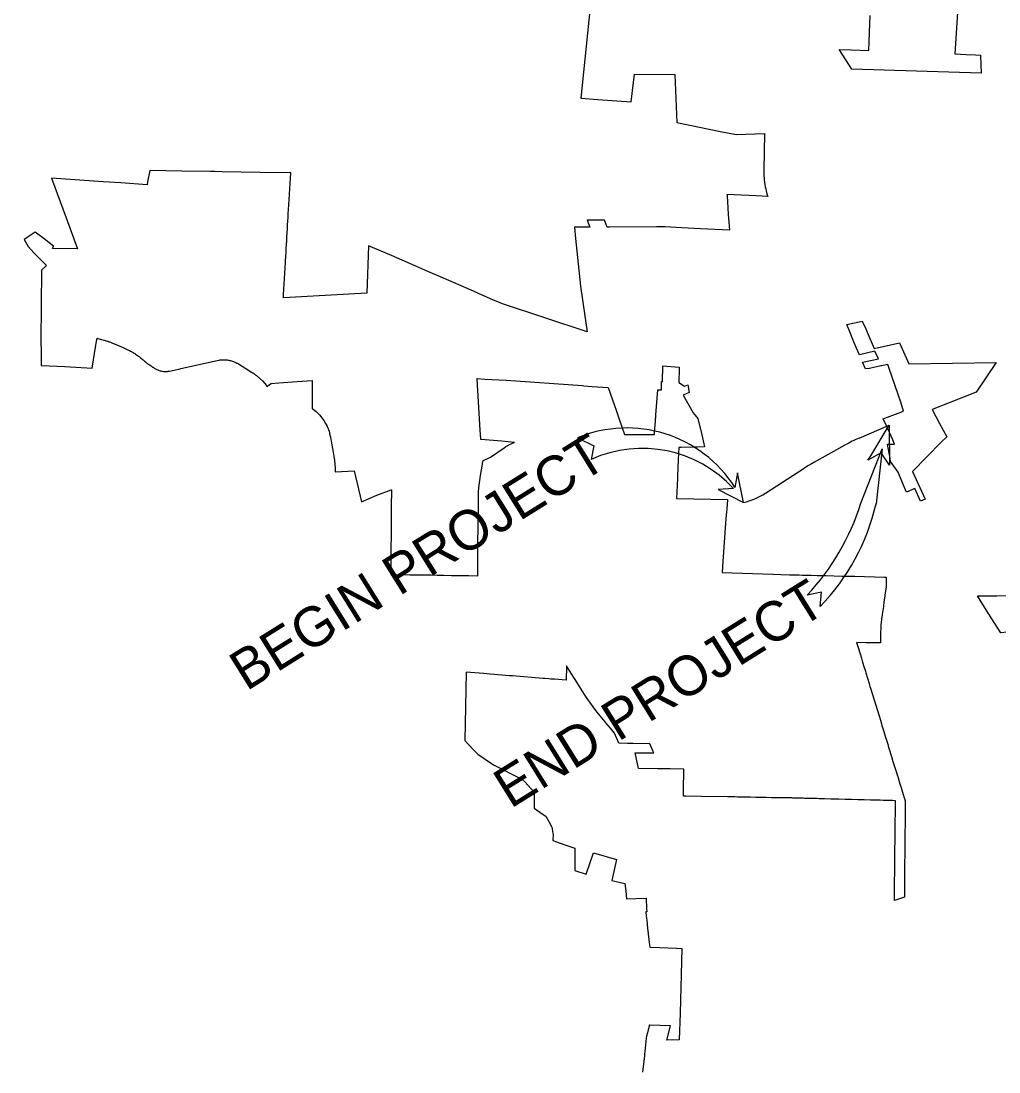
# Model space of a CAD drawing. Extents: x 2038094 to 2053858, y 751760 to 764312.
# Drawn here: x 2043353 to 2044647, y 758364 to 759754 of the extents above; entities that cross this region are included whole.
import ezdxf

# ---------------------------------------------------------------- set-up
doc = ezdxf.new("R2010")
doc.units = 0
for name, color, linetype in [('Old_Level_14', 7, 'Continuous'), ('Prop Horizontal Alignment', 7, 'Continuous'), ('Prop Shade Light', 7, 'Continuous'), ('Sheet Title CELL', 7, 'Continuous')]:
    doc.layers.add(name, color=color, linetype=linetype)

msp = doc.modelspace()

# ---------------------------------------------------------------- linework, layer by layer
at = {"layer": 'Old_Level_14'}
for p, q in [((2044463.9, 759116.1), (2044492.2, 759187.9)), ((2044492.2, 759187.9), (2044484.1, 759115.2)), ((2044295.5, 759135.4), (2044275.2, 759134))]:
    msp.add_line(p, q, dxfattribs=at)
msp.add_lwpolyline([(2044477.3, 759178.5), (2044501.4, 759219.1), (2044501.7, 759166.2), (2044490.9, 759182.5), (2044473.1, 759173)], close=True, dxfattribs=at)
for points in [[(2044089, 759202.3), (2044111, 759192), (2044107.5, 759173.9)], [(2044275.2, 759134), (2044308.7, 759116.8), (2044300.7, 759156.2), (2044297.5, 759136.9)], [(2044410.3, 758979.3), (2044411.8, 758998.1), (2044393, 758994.5)]]:
    msp.add_lwpolyline(points, dxfattribs=at)
for centre, radius, start, end in [((2044154.4, 759045.7), 169.7, 32.5095, 112.6622), ((2044174.8, 759024), 164.3, 42.6841, 114.1812), ((2044166.8, 759208), 311, 316.6494, 342.8091), ((2044206, 759178.3), 285.1, 315.7478, 347.23)]:
    msp.add_arc(centre, radius, start, end, dxfattribs=at)
at = {"layer": 'Prop Horizontal Alignment'}
for p, q in [((2044461.9, 759202.1), (2044501.4, 759219.1)), ((2044402.1, 759170), (2044443.4, 759193)), ((2044337.7, 759129.2), (2044389, 759162.1))]:
    msp.add_line(p, q, dxfattribs=at)
for centre, radius, start, end in [((2044540.8, 759018.3), 200, 113.2527, 119.1633), ((2044524, 758951.7), 250, 119.1633, 122.6814), ((2044286.4, 759209.1), 95, 283.6056, 302.6814)]:
    msp.add_arc(centre, radius, start, end, dxfattribs=at)
at = {"layer": 'Prop Shade Light'}
for points in [[(2044106.1, 759771.8), (2044093.7, 759651.7), (2044116, 759649.9), (2044160, 759646.7), (2044164.4, 759683.1), (2044217.8, 759682.8), (2044220.6, 759619.4), (2044278.3, 759607.6), (2044299, 759603.4), (2044336.6, 759604.6), (2044335.6, 759556.9), (2044335.6, 759554.6), (2044335.6, 759551.5), (2044335.7, 759548.6), (2044335.9, 759546.3), (2044336.1, 759543.6), (2044336.5, 759540.7), (2044337, 759536.8), (2044337.5, 759534.2), (2044338.1, 759531.6), (2044338.7, 759529), (2044339.7, 759525.1), (2044340.8, 759521.7), (2044325.7, 759522.3), (2044286.9, 759524), (2044287, 759523.6), (2044287.1, 759522.3), (2044288.1, 759506.3), (2044288.7, 759497.5), (2044289.4, 759487.7), (2044290.1, 759477.1), (2044251.9, 759478.9), (2044227.1, 759480.1), (2044205, 759481.2), (2044193.8, 759481.2), (2044131.7, 759481), (2044128.6, 759481), (2044125, 759490.3), (2044122, 759490.3), (2044102, 759490.2), (2044105.4, 759481), (2044099.5, 759481), (2044085.3, 759480.9), (2044086.7, 759466.1), (2044091.9, 759415.6), (2044093.2, 759403), (2044102, 759342.4), (2043990.2, 759379.4), (2043977.3, 759385), (2043959, 759392.9), (2043956.3, 759394.1), (2043951.6, 759396.2), (2043908.7, 759414.8), (2043891.1, 759422.4), (2043875.3, 759429.3), (2043843, 759443.3), (2043813, 759456.4), (2043810.7, 759393.6), (2043700.2, 759387.5), (2043700.4, 759392.1), (2043702.9, 759434.1), (2043703, 759436.3)], [(2044591.8, 759764.8), (2044588.3, 759710), (2044603.3, 759709.3), (2044615.7, 759708.8), (2044622.1, 759708.2), (2044622.2, 759707.6), (2044623.1, 759684.5), (2044451.9, 759689.7), (2044435.4, 759715.9), (2044451, 759715.4), (2044474.4, 759714.6), (2044474.9, 759726.8), (2044476.1, 759760.8)], [(2043703, 759436.3), (2043703.3, 759442.1), (2043703.7, 759447.9), (2043704, 759453), (2043704.3, 759458), (2043704.6, 759463), (2043704.9, 759468), (2043705.1, 759473), (2043705.5, 759478.9), (2043705.8, 759483.9), (2043706.1, 759488.9), (2043706.4, 759493.9), (2043706.7, 759498.9), (2043707, 759504.1), (2043707.3, 759510.5), (2043707.7, 759517.4), (2043708.2, 759524.5), (2043709.9, 759552.8), (2043709.7, 759552.8), (2043669.7, 759553.4), (2043619.3, 759554.2), (2043609.3, 759554.5), (2043603.7, 759554.6), (2043566, 759555.2), (2043523.4, 759555.9), (2043520.7, 759541), (2043519.9, 759536.9), (2043485.4, 759539.4), (2043461.7, 759541.1), (2043449.3, 759541.9), (2043393.6, 759545.7), (2043412.9, 759493.4), (2043428.1, 759452.3), (2043394.9, 759452.8), (2043396, 759455.7), (2043383.7, 759465.3), (2043372.1, 759474.4), (2043357.5, 759464.5), (2043362.7, 759455.3), (2043371.1, 759446.1), (2043382.8, 759434.3), (2043386.8, 759430.3), (2043380.5, 759423.9), (2043379.5, 759330.7), (2043380, 759315.9), (2043379.9, 759298), (2043411.1, 759296.5), (2043447.4, 759294.7), (2043452.2, 759325), (2043452.6, 759327.7), (2043453.8, 759334.1), (2043454.6, 759333.9), (2043454.9, 759333.8), (2043467.7, 759330.1), (2043468.1, 759330), (2043468.8, 759329.8), (2043469.5, 759329.5), (2043470.7, 759329.1), (2043471.7, 759328.7), (2043472.6, 759328.4), (2043473.5, 759328), (2043474.4, 759327.6), (2043479.8, 759325.3), (2043489, 759321.2), (2043494.5, 759318.7), (2043495.3, 759318.4), (2043496.8, 759317.7), (2043497.9, 759317.1), (2043498.9, 759316.6), (2043499.7, 759316.2), (2043500.8, 759315.6), (2043501.7, 759315.1), (2043502.8, 759314.4), (2043503.7, 759313.8), (2043504.7, 759313.2), (2043506, 759312.3), (2043507.2, 759311.4), (2043508.4, 759310.5), (2043509.4, 759309.8), (2043510.3, 759309), (2043511.4, 759308.1), (2043512.4, 759307.3), (2043513.5, 759306.3), (2043514.6, 759305.4), (2043515.5, 759304.6), (2043516.5, 759303.9), (2043517.9, 759302.8), (2043518.9, 759302), (2043519.8, 759301.3), (2043520.6, 759300.7), (2043521.8, 759299.8), (2043523, 759298.9), (2043524, 759298.3), (2043525.3, 759297.4), (2043526.2, 759296.8), (2043527.3, 759296), (2043528, 759295.6), (2043528.8, 759295), (2043529.5, 759294.6), (2043530.3, 759294.1)], [(2044474.6, 759336.7), (2044478.9, 759326.7), (2044481.4, 759320.6), (2044515.3, 759327.9), (2044525.5, 759304.2), (2044527.3, 759300.1), (2044642.9, 759302.1), (2044616.4, 759262.8), (2044580.8, 759248.7), (2044558.3, 759239.8), (2044568.1, 759221.5), (2044577.5, 759203.9), (2044570.4, 759196.7), (2044532.3, 759158), (2044548.9, 759121.4), (2044542.7, 759118.4), (2044535.2, 759135.2), (2044524.4, 759130.5), (2044520.6, 759139.7), (2044514.3, 759154.8), (2044513.4, 759157.1), (2044503.3, 759171.2), (2044502.6, 759175.1), (2044499.3, 759193.9), (2044508.6, 759194), (2044506.1, 759199.6), (2044497.5, 759219), (2044493.5, 759227.5), (2044499.1, 759229.7), (2044520.5, 759237.8), (2044516.9, 759249.6), (2044501.4, 759294), (2044499.6, 759299.5), (2044491.5, 759297.6), (2044490.5, 759297.4), (2044475.6, 759294), (2044470.2, 759293.6), (2044466.3, 759302.6), (2044487.3, 759306.9), (2044482.6, 759317.1), (2044462.2, 759312.2), (2044458, 759321.9), (2044453.5, 759332.4), (2044449.2, 759342.4), (2044445.3, 759352.3), (2044465.9, 759356.5), (2044470.5, 759346.5), (2044474.6, 759336.7)], [(2043530.3, 759294.1), (2043531.1, 759293.7), (2043532, 759293.1), (2043532.1, 759293.1), (2043533, 759292.6), (2043534, 759292.2), (2043535, 759291.8), (2043536.1, 759291.4), (2043537.2, 759291.1), (2043538.4, 759290.8), (2043539.6, 759290.5), (2043541, 759290.3), (2043542.1, 759290.2), (2043543.4, 759290.1), (2043544.9, 759290.1), (2043546, 759290.2), (2043546.7, 759290.2), (2043546.9, 759290.3), (2043547.9, 759290.4), (2043548.8, 759290.5), (2043549.8, 759290.7), (2043563.7, 759293.8), (2043564.5, 759294), (2043612.6, 759304.8), (2043615.1, 759305.2), (2043616, 759305.4), (2043616.8, 759305.4), (2043617.9, 759305.5), (2043618.1, 759305.6), (2043619.4, 759305.6), (2043620.8, 759305.7), (2043622.2, 759305.6), (2043623.5, 759305.6), (2043625.2, 759305.4), (2043626, 759305.3), (2043627.1, 759305.2), (2043627.8, 759305.1), (2043628, 759305), (2043628.8, 759304.8), (2043630.1, 759304.5), (2043631.4, 759304.2), (2043633, 759303.7), (2043634.4, 759303.2), (2043635.8, 759302.6), (2043637.5, 759301.9), (2043638.8, 759301.2), (2043639.3, 759300.9), (2043640.9, 759300), (2043650.6, 759294), (2043658.1, 759289.4), (2043659.4, 759288.5), (2043659.9, 759288.2), (2043660.7, 759287.7), (2043661.6, 759287.1), (2043662.2, 759286.6), (2043662.8, 759286.2), (2043663.3, 759285.8), (2043663.9, 759285.4), (2043664.6, 759284.8), (2043665.2, 759284.4), (2043672.5, 759277.8), (2043675.8, 759274.1), (2043678.9, 759270.3), (2043682, 759272.7), (2043683.9, 759274.3), (2043694, 759275), (2043718.3, 759276.7), (2043738.4, 759278), (2043738.1, 759240.9), (2043739, 759240.5), (2043743.8, 759236.8), (2043747.8, 759232.6), (2043751, 759228.7), (2043753.6, 759225.1), (2043755.8, 759221.5), (2043756.7, 759220.1), (2043757.5, 759218.6), (2043758.2, 759217.2), (2043758.9, 759215.7), (2043759.5, 759214.2), (2043760.1, 759212.6), (2043760.6, 759211), (2043761, 759209.5), (2043761.4, 759207.8), (2043762.5, 759203.2), (2043763.4, 759197.8), (2043764.2, 759193), (2043765.1, 759188.2), (2043765.9, 759183.4), (2043766.9, 759178.3), (2043767.6, 759172.6), (2043768.2, 759167.5), (2043768.5, 759162.4), (2043768.6, 759157.2), (2043793.7, 759158.8), (2043803.7, 759117.6), (2043824, 759126.4), (2043842.7, 759133.6), (2043843, 759133.7), (2043843, 759127)], [(2044151.3, 759206.6), (2044151.9, 759206.6), (2044172.8, 759206.7), (2044191.1, 759206.8), (2044191.7, 759215.3), (2044192.3, 759223.6), (2044193, 759232.8), (2044195.4, 759265.8), (2044200.4, 759265.8), (2044200.5, 759276.6), (2044200.5, 759276.8), (2044201.8, 759276.7), (2044201.9, 759297.4), (2044223.5, 759295.7), (2044223.5, 759294), (2044223.2, 759275.7), (2044230.6, 759270.6), (2044235.1, 759272.3), (2044236.9, 759262.3), (2044228.9, 759259), (2044242.1, 759235.6), (2044248.5, 759227.9), (2044253.6, 759206.3), (2044257.4, 759190.3), (2044248, 759190), (2044243.7, 759189.9), (2044226.5, 759189.6), (2044223.4, 759189.5), (2044222.5, 759173.9), (2044221.5, 759151.8), (2044221.3, 759148.6), (2044220.2, 759122.2)], [(2044005.7, 759196.4), (2043989.1, 759197.8), (2043961.2, 759200.1), (2043961.2, 759201), (2043960.5, 759212.3), (2043957, 759272.4), (2043956.6, 759280.7), (2043966.6, 759280.1), (2043994.9, 759278.7), (2044095.8, 759271.4), (2044097.7, 759271.1), (2044103, 759270.5), (2044108.6, 759270.1), (2044129.9, 759269.1), (2044138.1, 759245.3), (2044140.3, 759238.9), (2044144.4, 759226.9), (2044151.3, 759206.6)], [(2043958.5, 759136.3), (2043961, 759152.4), (2043963.4, 759167.4), (2043964.1, 759172.1), (2043974.3, 759177), (2043992.2, 759189.2), (2043994.6, 759190.8), (2043997.1, 759192.2), (2044000.1, 759193.9), (2044003.1, 759195.2), (2044005.7, 759196.4)], [(2043843, 759127), (2043843, 759125), (2043842.9, 759119.9), (2043842.8, 759105.2), (2043842.8, 759095.1), (2043842.8, 759093.9), (2043842.7, 759080.5), (2043842.7, 759077.2), (2043842.6, 759068.9), (2043842.5, 759060.8), (2043842.5, 759053.3), (2043842.4, 759045.8), (2043842.4, 759038.3), (2043842.4, 759037), (2043842.4, 759033.3), (2043842.4, 759030.3), (2043842.4, 759022), (2043842.4, 759021.8), (2043849.8, 759021.7), (2043867.3, 759021.4), (2043868.1, 759021.4), (2043874.8, 759021.3), (2043878.5, 759021.3), (2043882.3, 759021.2), (2043887.3, 759021.1), (2043895.6, 759021), (2043903.8, 759020.8), (2043912.3, 759020.7), (2043922.4, 759020.5), (2043931.3, 759020.3), (2043939.8, 759020.2), (2043944.6, 759020.1), (2043945.3, 759020.1), (2043957.4, 759019.9), (2043957.5, 759036.3), (2043957.5, 759043.6), (2043957.5, 759051.1), (2043957.5, 759051.5), (2043957.5, 759061.4), (2043957.5, 759062.3), (2043957.6, 759070.2), (2043957.7, 759077.7), (2043957.8, 759085.2), (2043958, 759092.6), (2043958.1, 759100.1), (2043958.2, 759110.6), (2043958.3, 759118.1), (2043958.4, 759130.5), (2043958.5, 759136.3)], [(2044220.2, 759122.2), (2044221.1, 759122.2), (2044287.5, 759120.6), (2044287, 759113.8), (2044286.6, 759108.9)], [(2044286.6, 759108.9), (2044286.6, 759108.4), (2044286.2, 759103.9), (2044285.6, 759095.8), (2044281.5, 759038.9), (2044280.4, 759024.1), (2044347.6, 759022), (2044347.9, 759022), (2044358.1, 759021.6), (2044369.5, 759021.4), (2044374.3, 759021.3), (2044380.6, 759021.1), (2044382.3, 759021), (2044386.9, 759020.9), (2044390.5, 759020.8), (2044398.4, 759020.6), (2044406.1, 759020.5), (2044414.3, 759020.3), (2044417.7, 759020.2), (2044439.4, 759019.6), (2044439.8, 759019.6), (2044443.4, 759019.5), (2044444.4, 759019.5), (2044452.1, 759019.3), (2044452.4, 759019.3), (2044453.4, 759019.3), (2044455.4, 759019.3), (2044495.2, 759018.3), (2044497.4, 759018.2), (2044497.4, 759006.4), (2044497.4, 759005.2), (2044495.9, 758994.5), (2044495.7, 758992.8), (2044494.6, 758985.4), (2044493.8, 758979.5), (2044493, 758974), (2044492.2, 758968.6), (2044492.1, 758967.8), (2044491.4, 758963.1), (2044490.7, 758957.7), (2044490.4, 758955.7), (2044490.3, 758951.3), (2044490.1, 758943.9), (2044489.9, 758935.8), (2044489.8, 758931.2), (2044482.9, 758931.2), (2044471, 758931.3), (2044458.4, 758931.5), (2044460.4, 758925), (2044463, 758916.6), (2044464.7, 758911.2), (2044466.3, 758905.9), (2044468.1, 758900), (2044470, 758893.9), (2044470.5, 758891.7), (2044474.8, 758877.5), (2044475.6, 758875.1), (2044476, 758873.6), (2044476.8, 758871.2), (2044485.8, 758841.9), (2044490.2, 758827.6), (2044490.2, 758827.4), (2044492.3, 758820.7), (2044492.3, 758820.5), (2044494.3, 758814.1), (2044496.2, 758807.9), (2044498.3, 758801.2), (2044499.9, 758795.8), (2044500.3, 758794.5), (2044502.4, 758787.8), (2044504.2, 758781.7), (2044504.4, 758781.1), (2044506.5, 758774.4), (2044508.5, 758767.7), (2044510.6, 758761), (2044512.3, 758755.6), (2044512.7, 758754.3), (2044515.6, 758744.9), (2044517.1, 758739.9), (2044517.7, 758737.8)], [(2044699.2, 758994), (2044728.4, 758993.7), (2044730.8, 758986.8), (2044732.3, 758982.9), (2044734.4, 758977.4), (2044736.5, 758972.3), (2044738.8, 758966.7), (2044670.3, 758948.6), (2044671.5, 758946.6), (2044669.7, 758946.4), (2044657.5, 758945.2), (2044649, 758944.4), (2044636.4, 758964.4), (2044633.6, 758968.9), (2044632.5, 758970.5), (2044629.8, 758974.9), (2044621.6, 758987.9), (2044618.1, 758993.5), (2044640.4, 758993.5), (2044643.9, 758993.5), (2044669.7, 758994.1), (2044699.2, 758994)], [(2044155.4, 758798.2), (2044143.7, 758798.4), (2044138.3, 758811.8), (2044132.7, 758818.3), (2044126.5, 758825.6), (2044125.7, 758826.6), (2044117.1, 758837.3), (2044112.3, 758843.5), (2044107.7, 758849.8), (2044102.1, 758857.8), (2044097.8, 758864.3), (2044088.4, 758879.2), (2044078.1, 758895.3), (2044074.5, 758900.9), (2044074.5, 758900.1), (2044074.1, 758881.7), (2044058.9, 758883)], [(2044058.9, 758883), (2044053.8, 758883.4), (2044051.1, 758883.6), (2044045.8, 758884), (2044043.3, 758884.3), (2044003.1, 758887.5), (2043999.4, 758887.8), (2043973.5, 758890), (2043965.4, 758890.5), (2043964.7, 758890.5), (2043941.8, 758892.4), (2043940.9, 758846.6), (2043940, 758802), (2043951.3, 758790.3), (2043957.3, 758784), (2043978, 758770), (2044015.8, 758751.1), (2044019.4, 758747.3), (2044031.9, 758733.9), (2044032, 758712.6), (2044042.7, 758705.2), (2044047.4, 758702.1), (2044051.2, 758694.9), (2044055.1, 758687.7), (2044055.5, 758685.6), (2044056.2, 758681.4), (2044056.9, 758678), (2044056.4, 758669.7), (2044072.4, 758664.2), (2044085.8, 758659.9), (2044085.6, 758643.3), (2044085.6, 758638.6), (2044085.5, 758632.2), (2044085.8, 758630)], [(2044517.7, 758737.8), (2044518.6, 758735.1), (2044520.3, 758729.3), (2044520.9, 758727.7), (2044521.7, 758725.3), (2044522.7, 758722.2), (2044522.6, 758710.7), (2044522.6, 758705.7), (2044522.5, 758699.5), (2044522.5, 758694), (2044522.4, 758688.5), (2044522.3, 758683), (2044522.3, 758677.5), (2044522.2, 758671.5), (2044522.2, 758665.5), (2044522.1, 758660), (2044522.1, 758654.5), (2044522, 758648.8), (2044521.9, 758642.6), (2044521.9, 758636.2), (2044521.8, 758629.8), (2044521.8, 758623.2), (2044521.7, 758616.9), (2044521.6, 758606.3), (2044521.5, 758597.8), (2044521.5, 758596.1), (2044521.5, 758595), (2044508.5, 758590.7), (2044508.5, 758597.8), (2044508.6, 758605), (2044508.7, 758616.8), (2044508.8, 758626.5), (2044508.9, 758634.5), (2044509, 758643.2), (2044509.1, 758651.5), (2044509.1, 758659.9), (2044509.2, 758668), (2044509.3, 758676.4), (2044509.4, 758685.7), (2044509.5, 758695.7), (2044509.6, 758705.6), (2044509.6, 758705.8), (2044509.6, 758710.6), (2044509.7, 758722.5), (2044505.7, 758722.6), (2044502, 758722.7), (2044499.9, 758722.8), (2044493.6, 758722.9), (2044489.5, 758723), (2044485.2, 758723.2), (2044483.3, 758723.2), (2044476.8, 758723.4), (2044468.4, 758723.6), (2044460, 758723.8), (2044451.6, 758724), (2044443.2, 758724.2), (2044434.8, 758724.5), (2044426.5, 758724.7), (2044425.3, 758724.7), (2044424.3, 758724.7), (2044415.9, 758724.9), (2044408.9, 758725.1), (2044406.3, 758725.2), (2044401.9, 758725.3), (2044397.3, 758725.4), (2044394.9, 758725.5), (2044389.6, 758725.6), (2044387.9, 758725.7), (2044381, 758725.8), (2044378.9, 758725.9), (2044373.9, 758726), (2044372.7, 758726.1), (2044366.9, 758726.2), (2044359.9, 758726.3), (2044353.1, 758726.4), (2044346.7, 758726.5), (2044345.9, 758726.5), (2044339, 758726.6), (2044331.9, 758726.8), (2044324.9, 758726.9), (2044317.9, 758727), (2044310.9, 758727.1), (2044300.9, 758727.3), (2044297.5, 758727.4), (2044287.6, 758727.5), (2044253.4, 758728.1), (2044232.6, 758728.5), (2044229.3, 758728.5), (2044229.3, 758735.5), (2044229.7, 758764.4), (2044211.6, 758764.6), (2044195.1, 758764.7), (2044169.8, 758765), (2044165.4, 758786), (2044190.2, 758785.8), (2044189.5, 758787.4), (2044184.9, 758797.9), (2044162.7, 758798), (2044155.4, 758798.2)], [(2044085.8, 758630), (2044086.9, 758629.7), (2044100.5, 758625.3), (2044110.3, 758653.6), (2044140.8, 758644.8), (2044134.8, 758617), (2044151.8, 758612.9), (2044153, 758602.8), (2044154.2, 758592.7), (2044180, 758593.4), (2044180.1, 758588.9), (2044180.3, 758584.5), (2044180.5, 758580.1), (2044180.7, 758575.7), (2044179.8, 758575.6), (2044180.2, 758570), (2044180.7, 758564.5), (2044181.3, 758558.9), (2044181.8, 758553.8), (2044184.5, 758531.6), (2044184.8, 758528.9)], [(2044227.2, 758527.2), (2044225.2, 758441.5), (2044223.5, 758406.4), (2044207.3, 758406), (2044212.1, 758424.9), (2044185.1, 758425.6), (2044184.2, 758425.6), (2044184, 758424.8), (2044183.8, 758424.1), (2044182.6, 758419.6), (2044181.6, 758415.7), (2044180.5, 758411.1), (2044180, 758408.5), (2044178.3, 758391), (2044177.9, 758387.5), (2044177.7, 758385.2), (2044175.3, 758363.3)], [(2044184.8, 758528.9), (2044197.7, 758528.4), (2044220.1, 758527.5), (2044220.4, 758527.5), (2044227.2, 758527.2)]]:
    msp.add_lwpolyline(points, dxfattribs=at)

# ---------------------------------------------------------------- texts
at = {"layer": 'Old_Level_14'}
for s, p in [('BEGIN PROJECT', (2043651.3, 758866.7)), ('END PROJECT', (2044000.6, 758711.3))]:
    msp.add_text(s, height=52.501, rotation=31.918, dxfattribs=at).set_placement(p)
at = {"layer": 'Sheet Title CELL'}
for s, height, rotation, p in [('See Sheet 1B For Conventional Symbols', 45, 31.918, (2043011.7, 759681.6)), ('VICINITY MAP', 108, 31.9164, (2044417.7, 757937.4))]:
    msp.add_text(s, height=height, rotation=rotation, dxfattribs=at).set_placement(p)

doc.saveas('drawing.dxf')
